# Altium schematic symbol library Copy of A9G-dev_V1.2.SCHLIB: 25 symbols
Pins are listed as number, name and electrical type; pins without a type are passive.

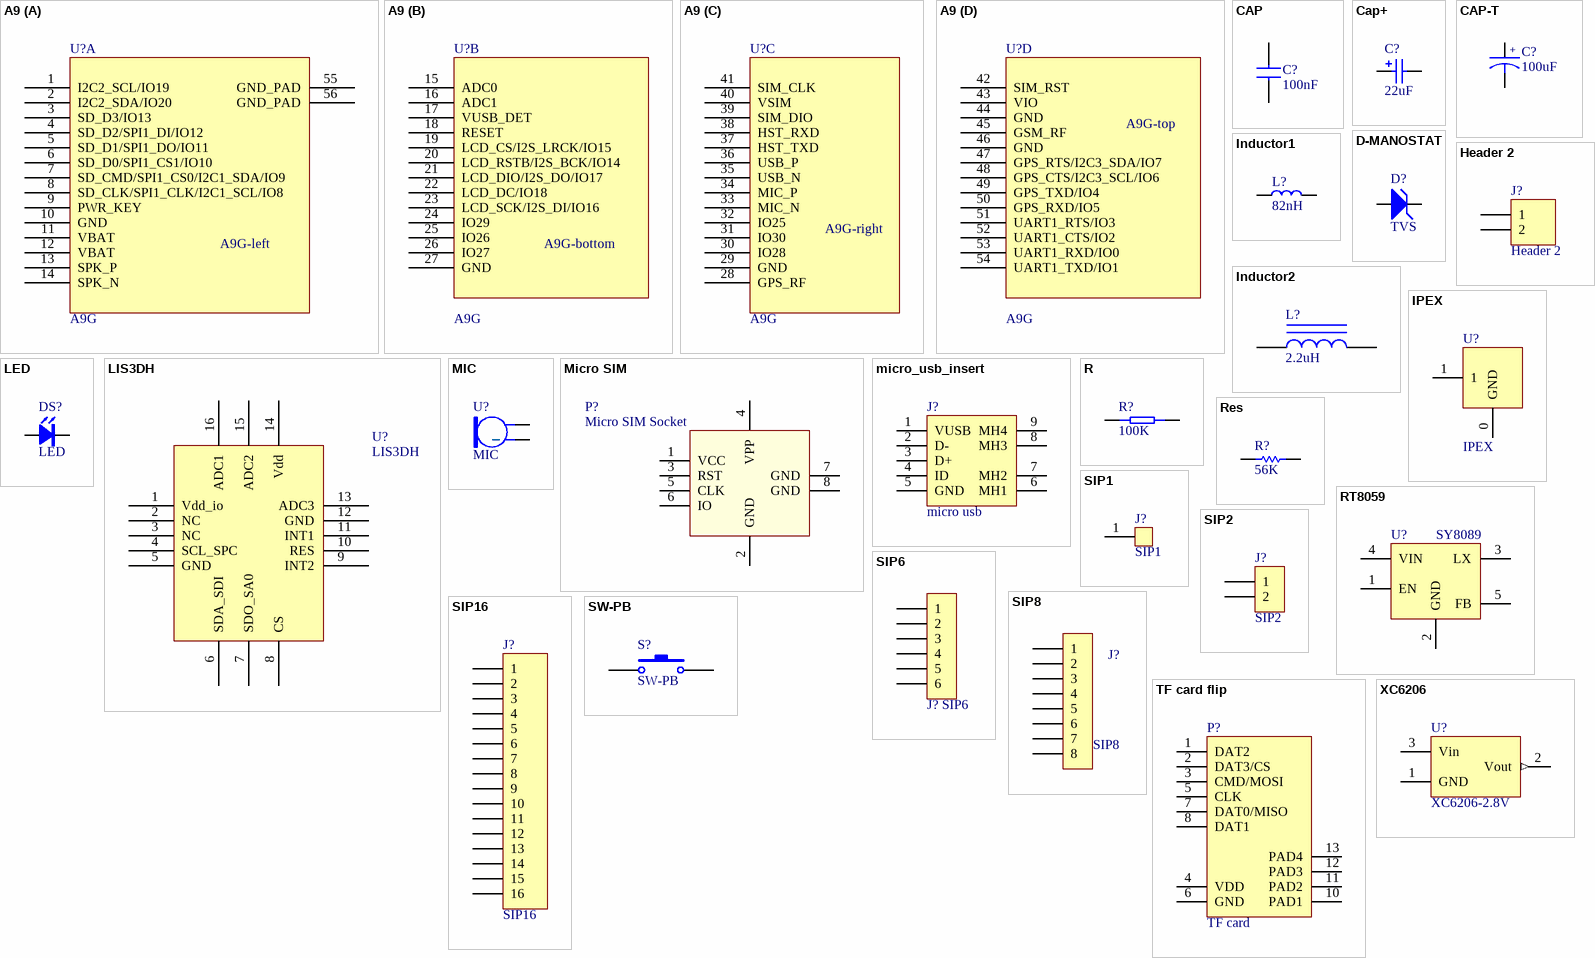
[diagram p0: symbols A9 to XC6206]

## A9
designator U?, comment A9G
footprint A9
part A pins: 1 I2C2_SCL/IO19, 2 I2C2_SDA/IO20, 3 SD_D3/IO13, 4 SD_D2/SPI1_DI/IO12, 5 SD_D1/SPI1_DO/IO11, 6 SD_D0/SPI1_CS1/IO10, 7 SD_CMD/SPI1_CS0/I2C1_SDA/IO9, 8 SD_CLK/SPI1_CLK/I2C1_SCL/IO8, 9 PWR_KEY, 10 GND, 11 VBAT, 12 VBAT, 13 SPK_P, 14 SPK_N, 55 GND_PAD, 56 GND_PAD
part B pins: 15 ADC0, 16 ADC1, 17 VUSB_DET, 18 RESET, 19 LCD_CS/I2S_LRCK/IO15, 20 LCD_RSTB/I2S_BCK/IO14, 21 LCD_DIO/I2S_DO/IO17, 22 LCD_DC/IO18, 23 LCD_SCK/I2S_DI/IO16, 24 IO29, 25 IO26, 26 IO27, 27 GND
part C pins: 28 GPS_RF, 29 GND, 30 IO28, 31 IO30, 32 IO25, 33 MIC_N, 34 MIC_P, 35 USB_N, 36 USB_P, 37 HST_TXD, 38 HST_RXD, 39 SIM_DIO, 40 VSIM, 41 SIM_CLK
part D pins: 42 SIM_RST, 43 VIO, 44 GND, 45 GSM_RF, 46 GND, 47 GPS_RTS/I2C3_SDA/IO7, 48 GPS_CTS/I2C3_SCL/IO6, 49 GPS_TXD/IO4, 50 GPS_RXD/IO5, 51 UART1_RTS/IO3, 52 UART1_CTS/IO2, 53 UART1_RXD/IO0, 54 UART1_TXD/IO1

## CAP
designator C?, comment 100nF
SMD-CAP
footprint 0603C
footprint 0805C
footprint 1206C
footprint C_CCB
footprint 0402C
pins: 1, 2

## Cap+
designator C?, comment 22uF
footprint B3528
footprint C0805
pins: 1, 2

## CAP-T
designator C?, comment 100uF
钽电容
footprint 6032C
footprint 7343C
footprint 3528C
footprint 3216C
pins: 1, 2

## D-MANOSTAT
designator D?, comment TVS
manostat diode
footprint DO-41
footprint DO-35
footprint 0603D
pins: A 1, K 2

## Header 2
designator J?
Header, 2-Pin
footprint HDR1X2 (Connector; Header; 2 Position)
signal-integrity model Connector
pins: 1, 2

## Inductor1
designator L?, comment 82nH
footprint L3330
footprint L0402
footprint L0603
footprint L0805
pins: 1, 2

## Inductor2
designator L?, comment 2.2uH
footprint L5050
footprint L3330
pins: 1, 2

## IPEX
designator U?
footprint IPEX
footprint IPEX_SHORT
pins: 0 GND, 1

## LED
designator DS?
footprint 0805D
footprint LED-5
footprint 0603D
footprint 0603D_R
footprint 0603D_B
pins: A 1, K 2

## LIS3DH
designator U?
footprint LGA-16
pins: 1 Vdd_io, 2 NC, 3 NC, 4 SCL_SPC, 5 GND, 6 SDA_SDI, 7 SDO_SA0, 8 CS, 9 INT2, 10 RES, 11 INT1, 12 GND, 13 ADC3, 14 Vdd, 15 ADC2, 16 ADC1

## MIC
designator U?
footprint SIP2-2.54
footprint MIC_4013_smt
footprint mic_4015
pins: 1, 2

## Micro SIM
designator P?, comment Micro SIM Socket
footprint SIM
pins: 1 VCC, 2 GND, 3 RST, 4 VPP, 5 CLK, 6 IO, 7 GND, 8 GND

## micro_usb_insert
designator J?, comment micro usb
footprint USB_MICRO_insert
pins: 1 VUSB, 2 D-, 3 D+, 4 ID, 5 GND, 6 MH1, 7 MH2, 8 MH3, 9 MH4

## R
designator R?, comment 100K
footprint 0805R
footprint R-AXIAL0.3
footprint R-AXIAL0.4
footprint 0402R
pins: 1, 2

## Res
designator R?, comment 56K
footprint R0402
footprint R0603
footprint R1206
footprint R0402-L
pins: 1, 2

## RT8059
designator U?, comment SY8089
footprint SOT23-5
pins: 1 EN "Chip Enable Mode Switch", 2 GND "Ground", 3 LX "Switching Output", 4 VIN "Power Input", 5 FB "Output Voltage Sense"

## SIP1
designator J?
Variable Resistor; Set Position: 0.5
footprint AXIAL-0.6 (Variable Resistor; 2 Leads)
simulation model VRES (Variable Resistor)
signal-integrity model Res Adj
footprint SIP1_2.54
pins: 1

## SIP2
designator J?
jointbar
footprint SIP2-2.0
footprint SIP2-2.54
footprint SIP2-2.54_short
pins: 1, 2

## SIP6
designator J?
jointbar
footprint SIP6-2.0
footprint SIP6-2.54
pins: 1, 2, 3, 4, 5, 6

## SIP8
designator J?
jointbar
footprint SIP8-2.0
footprint SIP8-2.54
footprint SIP8_1.27
pins: 1, 2, 3, 4, 5, 6, 7, 8

## SIP16
designator J?
jointbar
footprint SIP16-2.54
pins: 1, 2, 3, 4, 5, 6, 7, 8, 9, 10, 11, 12, 13, 14, 15, 16

## SW-PB
designator S?
Switch
footprint SPST-2 (Switch; 2 Leads)
footprint key2_3*4
pins: 1, 2

## TF card flip
designator P?, comment TF card
footprint TF_short
footprint TF_self-eject
pins: 1 DAT2, 2 DAT3/CS, 3 CMD/MOSI, 4 VDD, 5 CLK, 6 GND, 7 DAT0/MISO, 8 DAT1, 10 PAD1, 11 PAD2, 12 PAD3, 13 PAD4

## XC6206
designator U?, comment XC6206-2.8V
3.3V
footprint TO-92
footprint SOT-23
pins: 1 GND (power), 2 Vout (out), 3 Vin (power)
